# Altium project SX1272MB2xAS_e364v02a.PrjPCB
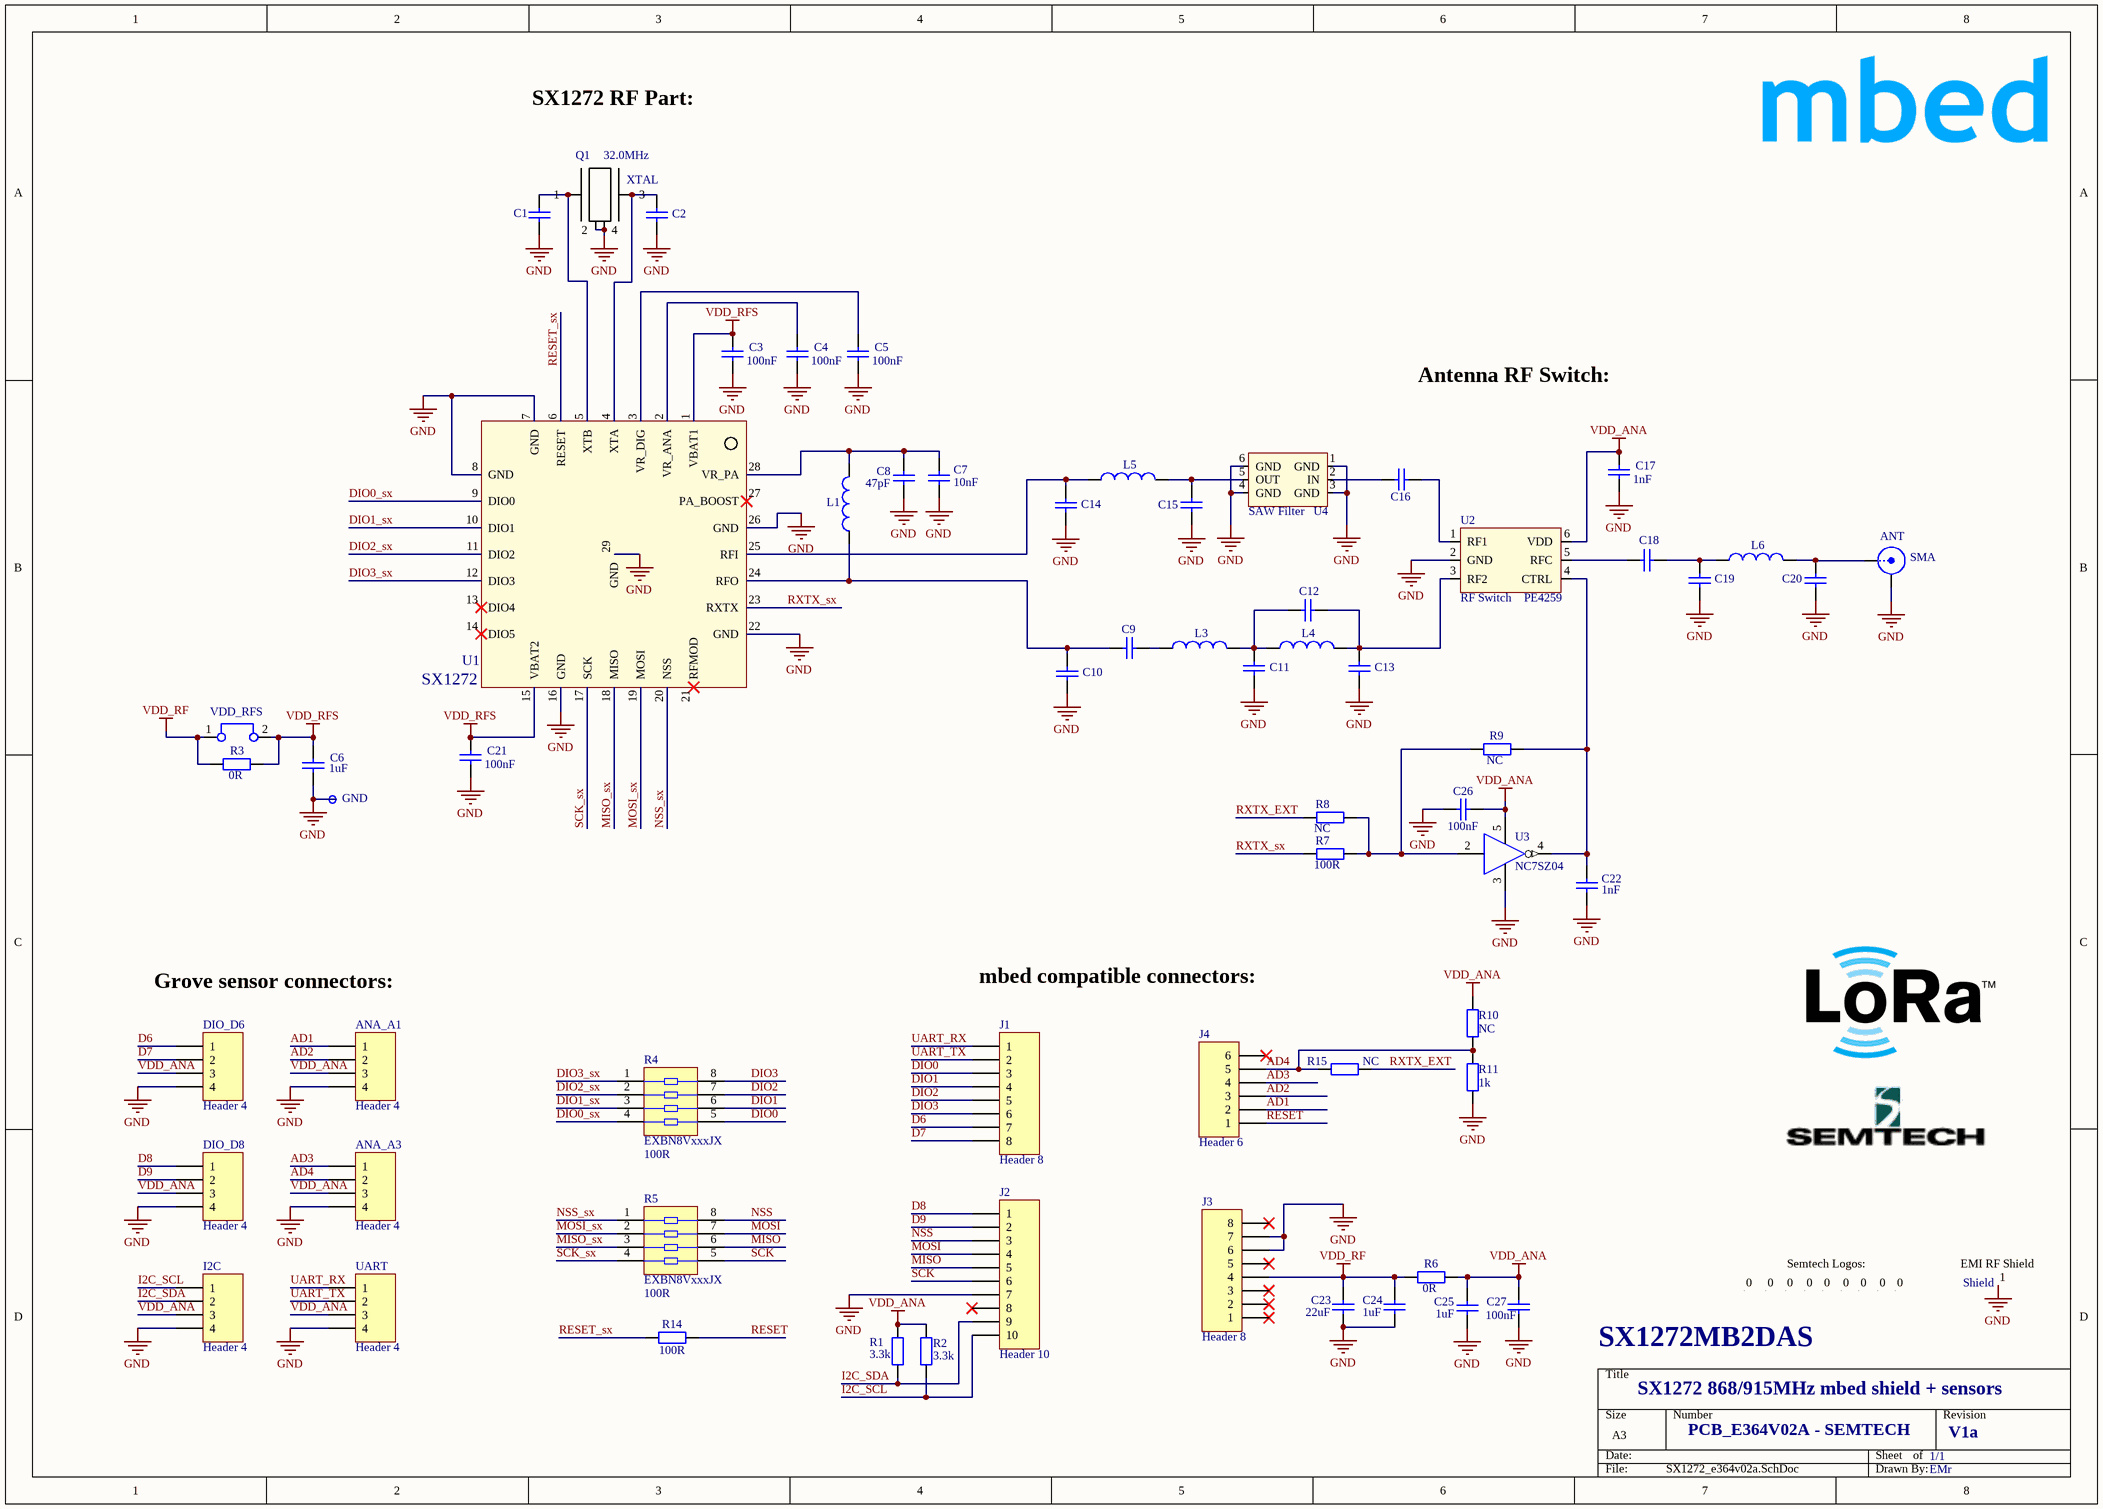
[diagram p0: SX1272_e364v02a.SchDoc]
1 sheet, 73 parts. Net scope: global (net labels, ports and power ports of the same name join across sheets).
Board file: SX1272_e364v02a.PcbDoc

## Sheet SX1272_e364v02a.SchDoc
size A3; DocumentNumber: 1; SheetNumber: 1; SheetTotal: 1

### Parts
ANA_A1  Header 4  [1125S-4P_connector]
ANA_A3  Header 4  [1125S-4P_connector]
ANT  SMA  [SMA END LAUNCH JACK RECEPTACLE SHORT]
C1  Cap  [rlc_402_smd]  (value not drawn)
C2  Cap  [rlc_402_smd]  (value not drawn)
C3  value 100nF  [rlc_402_smd]  (hidden comment: Cap)
C4  value 100nF  [rlc_402_smd]  (hidden comment: Cap)
C5  value 100nF  [rlc_402_smd]  (hidden comment: Cap)
C6  value 1uF  [rlc_603_smd]  (hidden comment: Cap)
C7  value 10nF  [rlc_402_smd]  (hidden comment: Cap)
C8  value 47pF  [rlc_402_smd]  (hidden comment: Cap)
C9  Cap  [rlc_402_smd]  (value not drawn)
C10  Cap  [rlc_402_smd]  (value not drawn)
C11  Cap  [rlc_402_smd]  (value not drawn)
C12  Cap  [rlc_402_smd]  (value not drawn)
C13  Cap  [rlc_402_smd]  (value not drawn)
C14  Cap  [rlc_402_smd]  (value not drawn)
C15  Cap  [rlc_402_smd]  (value not drawn)
C16  Cap  [rlc_402_smd]  (value not drawn)
C17  value 1nF  [rlc_402_smd]  (hidden comment: Cap)
C18  Cap  [rlc_402_smd]  (value not drawn)
C19  Cap  [rlc_402_smd]  (value not drawn)
C20  Cap  [rlc_402_smd]  (value not drawn)
C21  value 100nF  [rlc_402_smd]  (hidden comment: Cap)
C22  value 1nF  [rlc_402_smd]  (hidden comment: Cap)
C23  value 22uF  [rlc_805_smd]  (hidden comment: Cap)
C24  value 1uF  [rlc_603_smd]  (hidden comment: Cap)
C25  value 1uF  [rlc_603_smd]  (hidden comment: Cap)
C26  value 100nF  [rlc_402_smd]  (hidden comment: Cap)
C27  value 100nF  [rlc_402_smd]  (hidden comment: Cap)
DIO_D6  Header 4  [1125S-4P_connector]
DIO_D8  Header 4  [1125S-4P_connector]
GND  Test Pin  [pin_1mm]  (value not drawn)
I2C  Header 4  [1125S-4P_connector]
J1  Header 8  [HDR1X8]
J2  Header 10  [HDR1X10]
J3  Header 8  [HDR1X8]
J4  Header 6  [HDR1X6]
L1  Inductor  [rlc_402_smd]  (value not drawn)
L3  Inductor  [rlc_402_smd]  (value not drawn)
L4  Inductor  [rlc_402_smd]  (value not drawn)
L5  Inductor  [rlc_402_smd]  (value not drawn)
L6  Inductor  [rlc_402_smd]  (value not drawn)
Logo_Bot  Logo symbol  [logo_semtech_horiz_size4]  (value not drawn)
Logo_ESD  Logo symbol  [Logo ESD]  (value not drawn)
Logo_Lora_Bot  Logo symbol  [Logo LoRa Size4]  (value not drawn)
Logo_Lora_Top  Logo symbol  [Logo LoRa Size3]  (value not drawn)
Logo_mbed_2  Logo symbol  [logo mbed 2]  (value not drawn)
Logo_mbed_enabled  Logo symbol  [Logo mbed enabled 2]  (value not drawn)
Logo_Recycling1  Logo symbol  [Logo Recycling1]  (value not drawn)
Logo_Semtech_S  Logo symbol  [Logo_Semtech_S_2]  (value not drawn)
Logo_Semtech_S2  Logo symbol  [logo_semtech_horiz_size2]  (value not drawn)
Q1  XTAL  value 32.0MHz  [nd2016da]
R1  value 3.3k  [rlc_402_smd]  (hidden comment: Resistor)
R2  value 3.3k  [rlc_402_smd]  (hidden comment: Resistor)
R3  value 0R  [rlc_603_smd]  (hidden comment: Resistor)
R4  EXBN8VxxxJX  value 100R  [EXB28V]
R5  EXBN8VxxxJX  value 100R  [EXB28V]
R6  value 0R  [rlc_603_smd]  (hidden comment: Resistor)
R7  value 100R  [rlc_402_smd]  (hidden comment: Resistor)
R8  value NC  [rlc_402_smd]  (hidden comment: Resistor)
R9  value NC  [rlc_402_smd]  (hidden comment: Resistor)
R10  value NC  [rlc_402_smd]  (hidden comment: Resistor)
R11  value 1k  [rlc_402_smd]  (hidden comment: Resistor)
R14  value 100R  [rlc_402_smd]  (hidden comment: Resistor)
R15  value NC  [rlc_402_smd]  (hidden comment: Resistor)
Shield  Logo symbol  [BMIS-205-F - Shield]  (value not drawn)
U1  SX1272  [vqfn28_6x6mm]
U2  RF Switch  value PE4259  [SC70-6]
U3  NC7SZ04  [SC70-5]
U4  SAW Filter  [DCC6C_3.0x3.0mm]
UART  Header 4  [1125S-4P_connector]
VDD_RFS  Jumper  [bridge_254mm]  (value not drawn)

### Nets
GND: ANA_A1.4 ANA_A3.4 ANT.2(GND) C1.1 C2.1 C3.1 C4.1 C5.1 C6.1 C7.1 C8.1 C10.1 C11.1 C13.1 C14.1 C15.1 C17.1 C19.1 C20.1 C21.1 C22.2 C23.1 C24.1 C25.1 C26.1 C27.1 DIO_D6.4 DIO_D8.4 GND.1(pin) I2C.4 J2.7 J3.6 J3.7 Q1.2 Q1.4 R11.2 Shield.1 U1.7(GND) U1.8(GND) U1.16(GND) U1.22(GND) U1.26(GND) U1.29(GND) U2.2(GND) U3.3(GND) U4.1(GND) U4.3(GND) U4.4(GND) U4.6(GND) UART.4
VDD_ANA: ANA_A1.3 ANA_A3.3 C17.2 C25.2 C26.2 C27.2 DIO_D6.3 DIO_D8.3 I2C.3 R1.2 R2.2 R6.1 R10.1 U2.6(VDD) U3.5(VCC) UART.3
VDD_RF: C23.2 C24.2 J3.4 R3.2 R6.2 VDD_RFS.1
VDD_RFS: C3.2 C6.2 C21.2 R3.1 U1.1(VBAT1) U1.15(VBAT2) VDD_RFS.2
AD1: ANA_A1.1 J4.2
AD2: ANA_A1.2 J4.3
AD3: ANA_A3.1 J4.4
AD4: ANA_A3.2 J4.5 R10.2 R11.1 R15.2
D6: DIO_D6.1 J1.7
D7: DIO_D6.2 J1.8
D8: DIO_D8.1 J2.1
D9: DIO_D8.2 J2.2
DIO0: J1.3 R4.5
DIO0_sx: R4.4 U1.9(DIO0)
DIO1: J1.4 R4.6
DIO1_sx: R4.3 U1.10(DIO1)
DIO2: J1.5 R4.7
DIO2_sx: R4.2 U1.11(DIO2)
DIO3: J1.6 R4.8
DIO3_sx: R4.1 U1.12(DIO3)
I2C_SCL: I2C.1 J2.10 R2.1
I2C_SDA: I2C.2 J2.9 R1.1
MISO: J2.5 R5.6
MISO_sx: R5.3 U1.18(MISO)
MOSI: J2.4 R5.7
MOSI_sx: R5.2 U1.19(MOSI)
NSS: J2.3 R5.8
NSS_sx: R5.1 U1.20(NSS)
RESET: J4.1 R14.2
RESET_sx: R14.1 U1.6(RESET)
RXTX_EXT: R8.2 R15.1
RXTX_sx: R7.2 U1.23(RXTX)
SCK: J2.6 R5.5
SCK_sx: R5.4 U1.17(SCK)
UART_RX: J1.1 UART.1
UART_TX: J1.2 UART.2
NetANT_1: ANT.1(Signal) C20.2 L6.2
NetC1_2: C1.2 Q1.1 U1.5(XTB)
NetC2_2: C2.2 Q1.3 U1.4(XTA)
NetC4_2: C4.2 U1.2(VR_ANA)
NetC5_2: C5.2 U1.3(VR_DIG)
NetC7_2: C7.2 C8.2 L1.2 U1.28(VR_PA)
NetC9_1: C9.1 L3.1
NetC9_2: C9.2 C10.2 L1.1 U1.24(RFO)
NetC11_2: C11.2 C12.2 L3.2 L4.1
NetC12_1: C12.1 C13.2 L4.2 U2.3(RF2)
NetC14_2: C14.2 L5.1 U1.25(RFI)
NetC15_2: C15.2 L5.2 U4.5(OUT)
NetC16_1: C16.1 U2.1(RF1)
NetC16_2: C16.2 U4.2(IN)
NetC18_1: C18.1 C19.2 L6.1
NetC18_2: C18.2 U2.5(RFC)
NetC22_1: C22.1 R9.1 U2.4(CTRL) U3.4(Y)
NetR7_1: R7.1 R8.1 R9.2 U3.2(A)

Not connected (* = marked no-connect by the designer): J2 8*; J3 1* 2* 3* 5* 8*; J4 6*; Logo_Bot 0; Logo_ESD 0; Logo_Lora_Bot 0; Logo_Lora_Top 0; Logo_mbed_2 0; Logo_mbed_enabled 0; Logo_Recycling1 0; Logo_Semtech_S 0; Logo_Semtech_S2 0; U1 13(DIO4)* 14(DIO5)* 21(RFMOD)* 27(PA_BOOST)*

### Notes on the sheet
- SX1272 RF Part:
- Antenna RF Switch:
- Grove sensor connectors:
- mbed compatible connectors:
- Semtech Logos:
- (near Shield) EMI RF Shield
- SX1272MB2DAS
- SX1272 868/915MHz mbed shield + sensors
- PCB_E364V02A - SEMTECH
- 1/1
- V1a
- EMr

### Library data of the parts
ANA_A1 ANA_A3 DIO_D6 DIO_D8 I2C UART = Header 4: Header, 4-Pin
ANT = SMA: SMA Straight Connector
C1 = Cap: Capacitor SMD; Value: 18pnF
C2 = Cap: Capacitor SMD; Value: 18pF
C3-C8 C17 C21-C27 = Cap: Capacitor SMD
C9-C16 C18 = Cap: Capacitor SMD; Value: 100nF
C19 C20 = Cap: Capacitor SMD; Value: NC
GND = test_pin
J1 J3 = Header 8: Header, 8-Pin
J2 = Header 10: Header, 10-Pin
J4 = Header 6: Header, 6-Pin
L1 L3-L5 = Inductor: Inductor SMD; Code_IEC: 1005; Value: VAL?
L6 = Inductor: Inductor SMD; Code_IEC: 1005; Value: 0R
Logo_Bot Logo_ESD Logo_Lora_Bot Logo_Lora_Top Logo_mbed_2 Logo_mbed_enabled Logo_Recycling1 Logo_Semtech_S Logo_Semtech_S2 = Logo: Schematic symbol for Logo
Q1 = xtal_gnd: Crystal with GND pins
R1-R3 R6-R11 R14 R15 = Resistor: Resistor SMD - IEC symbol version
R4 R5 = EXBN8VxxxJX: Mini-Flat Package, Isolated Resistor Network, 0.031 W/resistor
Shield = Shield: Shield - EMI Gasket - Standard Surface Mount Shields
U1 = SX1272: SX1272 - Low Power Integrated UHF Transceiver with Lora technology
U2 = PE4259 RF Switch: PE4259 Peregrine RF Switch
U3 = NC7SZ04: NC7SZ04 - TinyLogic HS Single Inverter - Fairchild Semi
U4 = SAW Filter: SAW Filter - Bandpass - TEMEX type
VDD_RFS = Jumper: Jumper Wire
